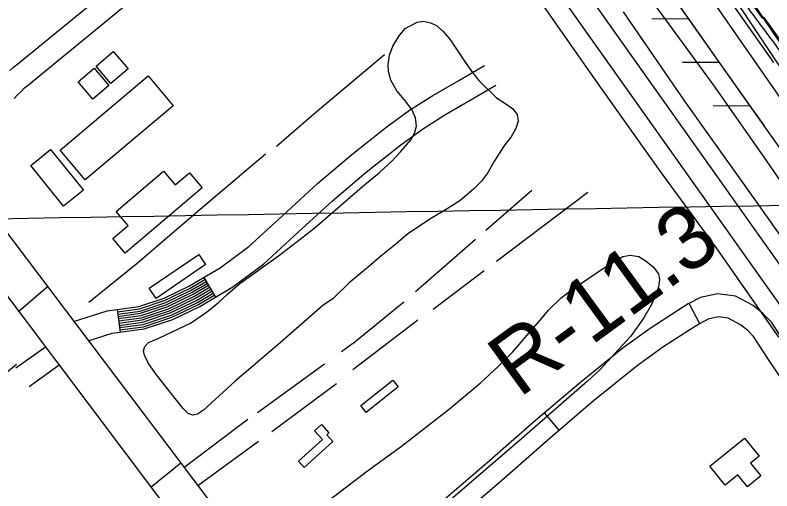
# Model space of a CAD drawing. Extents: x 3892998 to 3931244, y 278583 to 304547.
# Drawn here: x 3909141 to 3910137, y 289921 to 290546 of the extents above; entities that cross this region are included whole.
import ezdxf

# ---------------------------------------------------------------- set-up
doc = ezdxf.new("R2010")
doc.units = 0
for name, color, linetype in [('V-BLDG-OTLN', 7, 'Continuous'), ('V-GRID-MAJR', 7, 'Continuous'), ('V-LEVE-TOET', 7, 'Continuous'), ('V-RIVR-EDGE', 7, 'Continuous'), ('V-RIVR-RANG-IDEN', 7, 'Continuous'), ('V-ROAD-CNTR', 7, 'Continuous'), ('V-RRAP-FSHR', 7, 'Continuous'), ('V-RRAP-RVMT', 7, 'Continuous'), ('V-SITE-VEGE', 7, 'Continuous'), ('V-SURV-LINE', 7, 'Continuous'), ('V-TOPO-MINR', 7, 'Continuous'), ('V-TOPO-SHOR', 7, 'Continuous'), ('V-TOPO-WATR', 7, 'Continuous')]:
    doc.layers.add(name, color=color, linetype=linetype)

msp = doc.modelspace()

# ---------------------------------------------------------------- linework, layer by layer
at = {"layer": 'V-BLDG-OTLN'}
for points in [[(3909270.17, 290498.76), (3909289.69, 290476.08), (3909267.21, 290456.74), (3909247.69, 290479.42)], [(3909245.06, 290476.59), (3909264.48, 290453.81), (3909243.57, 290435.98), (3909224.15, 290458.76)], [(3909349.1, 290427.42), (3909233.34, 290329.81), (3909200.35, 290368.94), (3909316.11, 290466.54)], [(3909187.87, 290369.85), (3909230.97, 290316.39), (3909204.69, 290295.21), (3909161.59, 290348.67)], [(3909387.44, 290319.51), (3909286, 290233.45), (3909269.51, 290252.88), (3909289.75, 290270.06), (3909274.16, 290288.43), (3909336.58, 290341.39), (3909351.87, 290323.38), (3909370.65, 290339.31)], [(3909391.78, 290218.64), (3909326.68, 290174.19), (3909317.67, 290187.39), (3909382.77, 290231.83)], [(3909645.47, 290057.65), (3909603.3, 290024.11), (3909596.14, 290033.12), (3909638.31, 290066.65)], [(3909559.1, 289985.96), (3909521.73, 289951.97), (3909514.27, 289960.17), (3909545.45, 289988.53), (3909535.15, 289999.84), (3909544.25, 290008.13), (3909554.2, 289997.18), (3909551.3, 289994.54)], [(3910055.39, 289953.5), (3910101.26, 289990.48), (3910120.37, 289966.78), (3910108.89, 289957.52), (3910122.43, 289940.72), (3910104.91, 289926.6), (3910092.43, 289942.08), (3910075.57, 289928.48)]]:
    msp.add_lwpolyline(points, close=True, dxfattribs=at)
at = {"layer": 'V-GRID-MAJR'}
msp.add_spline([(3897162.87, 290075.22), (3902475.55, 290165.25), (3907788.21, 290256.05), (3913100.86, 290347.62), (3918413.49, 290439.97), (3923726.11, 290533.09), (3929038.72, 290626.99)], degree=3, dxfattribs=at)
at = {"layer": 'V-LEVE-TOET'}
for points in [[(3910146.31, 290123.1), (3910063.61, 290241.09), (3909990.62, 290340.83), (3909904.47, 290462.04), (3909815.64, 290589.3)], [(3909941.53, 290550.7), (3910022.07, 290433.29), (3910116.71, 290300.67), (3910208.99, 290170.6)]]:
    msp.add_lwpolyline(points, dxfattribs=at)
at = {"layer": 'V-RIVR-EDGE'}
msp.add_spline([(3909865.84, 290928.21), (3909862.62, 290923.11), (3909860.68, 290922.62), (3909860.67, 290920.68), (3909870.35, 290905.12), (3909881.93, 290877.89), (3909893.54, 290856.5), (3909906.13, 290843.84), (3909921.61, 290817.58), (3909937.09, 290794.71), (3909948.22, 290777.2), (3909977.73, 290734.39), (3910003.37, 290694.51), (3910040.65, 290645.85), (3910078.4, 290595.25), (3910114.21, 290544.17), (3910151.48, 290493.58), (3910181.95, 290444.45), (3910200.82, 290413.32), (3910226.93, 290368.58), (3910256.93, 290323.83), (3910278.7, 290289.3), (3910307.74, 290250.37), (3910325.16, 290226.53), (3910363.87, 290167.19), (3910391.44, 290124.87), (3910427.73, 290068.94), (3910449.5, 290036.83), (3910504.18, 289956.56), (3910522.07, 289926.9), (3910550.12, 289879.72), (3910562.21, 289857.35), (3910573.34, 289842.27), (3910610.65, 289806.73), (3910620.82, 289794.07), (3910623.21, 289779.99), (3910634.83, 289764.42), (3910664.83, 289724.03), (3910692.43, 289689.49), (3910710.83, 289668.07), (3910721.01, 289660.28), (3910770.89, 289605.28), (3910782.51, 289588.74), (3910807.66, 289548.37), (3910835.72, 289503.62), (3910862.83, 289470.04), (3910892.35, 289425.78), (3910920.41, 289383.46), (3910947.99, 289342.6), (3910968.78, 289304.67), (3911000.23, 289260.88), (3911019.59, 289231.7), (3911055.91, 289191.3), (3911085.45, 289159.66), (3911118.86, 289116.84), (3911139.19, 289091.05), (3911160.97, 289062.35), (3911184.19, 289025.87), (3911223.42, 288981.58), (3911281.53, 288916.36), (3911313, 288876.94), (3911328.5, 288859.42), (3911346.41, 288837.53), (3911371.58, 288801.04), (3911404.48, 288751.91), (3911426.73, 288715.43), (3911446.57, 288687.7), (3911479.01, 288646.83), (3911529.35, 288582.12), (3911550.65, 288552.92), (3911609.2, 288468.28), (3911644.54, 288421.09), (3911676.97, 288378.76), (3911701.17, 288348.1), (3911741.37, 288303.81), (3911770.9, 288264.88), (3911788.8, 288235.7), (3911834.27, 288164.69), (3911857.49, 288130.15), (3911884.6, 288092.69), (3911915.56, 288045.51), (3911921.85, 288035.78), (3911928.64, 288029.93), (3911972.62, 287945.81), (3911992.92, 287906.42), (3912000.64, 287886.98), (3912014.67, 287866.55), (3912026.77, 287848.06), (3912066.44, 287785.32), (3912084.8, 287750.79), (3912094.47, 287732.8), (3912094.94, 287726), (3912096.85, 287711.43), (3912096.35, 287704.63), (3912095.36, 287700.26), (3912088.55, 287695.91), (3912085.64, 287696.89), (3912073.03, 287702.26), (3912062.35, 287706.17), (3912054.1, 287706.19), (3912051.18, 287704.26), (3912049.22, 287697.95), (3912054.05, 287685.8), (3912068.56, 287663.91), (3912113.05, 287586.58), (3912136.73, 287540.87), (3912153.66, 287513.63), (3912163.84, 287503.9), (3912187.57, 287479.56), (3912207.42, 287453.28), (3912216.14, 287445.98), (3912226.8, 287436.24), (3912240.84, 287416.78), (3912253.42, 287397.81), (3912271.31, 287366.2), (3912283.87, 287341.4), (3912284.84, 287338.97), (3912290.18, 287337.98), (3912303.79, 287344.26), (3912317.4, 287350.54), (3912319.83, 287350.54), (3912322.75, 287350.53), (3912327.59, 287345.66), (3912328.54, 287338.37), (3912335.79, 287321.36), (3912348.36, 287299.96), (3912369.18, 287275.14), (3912380.33, 287265.4), (3912402.15, 287253.21), (3912416.69, 287243.46), (3912434.16, 287238.07), (3912456.94, 287220.05), (3912481.62, 287183.56), (3912501.93, 287148.06), (3912512.56, 287124.73), (3912531.4, 287085.83), (3912550.27, 287059.56), (3912569.64, 287034.26), (3912593.34, 286996.8), (3912613.67, 286968.1), (3912632.04, 286936.49), (3912645.1, 286912.66), (3912660.58, 286888.83), (3912675.09, 286867.42), (3912698.32, 286835.31), (3912720.05, 286784.75), (3912736.96, 286747.81), (3912742.28, 286740.02), (3912755.33, 286715.22), (3912761.6, 286696.75), (3912774.14, 286660.3), (3912779.9, 286635.52), (3912793.38, 286585.46), (3912797.22, 286569.43), (3912803.96, 286543.67), (3912804.41, 286532.02)], degree=3, dxfattribs=at)
at = {"layer": 'V-ROAD-CNTR'}
for p, q in [((3909389.43, 290201.64), (3909404.68, 290175.8)), ((3909275.26, 290159.43), (3909279.29, 290129.71)), ((3910042.2, 290140.9), (3910028.3, 290167.48)), ((3909857.21, 290000.69), (3909837.79, 290023.55))]:
    msp.add_line(p, q, dxfattribs=at)
for points in [[(3905312.49, 295227.11), (3905668.18, 294755.9), (3905995.86, 294324.81), (3906423.56, 293758.76), (3906727.79, 293356.24), (3907205.27, 292726.92), (3907628.01, 292163.31), (3908430.47, 291100.88), (3908883.88, 290504.6), (3909506.66, 289678.12), (3910240.41, 288708.06), (3910610.65, 288220.87)], [(3906034.21, 294352.1), (3906739.31, 293416.78), (3907556.81, 292335.42), (3908052.71, 291678.74), (3908621.74, 290930.17), (3909105.02, 290293.11), (3909494.77, 289778.17), (3910015.52, 289090.83), (3910630.79, 288278.73)], [(3909134.08, 290473.51), (3909139.08, 290477.91), (3909144.72, 290482.56), (3909283.58, 290596.54), (3909308.36, 290617.64), (3909333.43, 290638.69), (3909358.62, 290659.58), (3909383.96, 290680.29), (3909409.44, 290700.84), (3909435.07, 290721.24), (3909454.31, 290736.22), (3909473.36, 290751.23), (3909492.33, 290766.36), (3909511.2, 290781.58), (3909529.98, 290796.92), (3909548.81, 290812.47), (3909559.57, 290821.02), (3909570.41, 290829.4), (3909581.34, 290837.62), (3909592.38, 290845.68), (3909603.5, 290853.59), (3909612.29, 290859.65)], [(3909139.82, 290436.8), (3909144.26, 290441.61), (3909148.86, 290446.25), (3909153.62, 290450.74), (3909158.53, 290455.07), (3909163.77, 290459.39), (3909302.83, 290573.52)], [(3909217.98, 290143.86), (3909262.27, 290157.67), (3909304.12, 290163.35), (3909337.38, 290174.45), (3909369.89, 290190.11), (3909410.91, 290214.32), (3909448.81, 290242.2), (3909493.57, 290283.27), (3909539.03, 290325.02), (3909584.28, 290363.13), (3909630.68, 290399.92), (3909660.24, 290421.38), (3909690.96, 290440.98), (3909725.03, 290460.79), (3909758.83, 290480.44)], [(3909237.22, 290118.44), (3909268.8, 290128.29), (3909310.94, 290134), (3909348.68, 290146.59), (3909384.05, 290163.63), (3909427.47, 290189.25), (3909467.9, 290219), (3909513.85, 290261.17), (3909558.85, 290302.48), (3909603.27, 290339.9), (3909648.82, 290376.02), (3909677.14, 290396.57), (3909706.58, 290415.36), (3909740.11, 290434.85), (3909773.91, 290454.5)], [(3909760.55, 290263.72), (3909821.08, 290316.4)], [(3909895.08, 290313.36), (3909774.6, 290222.48)], [(3909667.94, 290183.12), (3909746.96, 290251.9)], [(3909758.61, 290210.42), (3909691.22, 290159.6)], [(3909275.66, 290156.46), (3909304.8, 290160.41), (3909338.51, 290171.66), (3909371.31, 290187.46), (3909390.95, 290199.05)], [(3909183.6, 290189.29), (3909145.95, 290156.81)], [(3909276.06, 290153.49), (3909305.48, 290157.48), (3909339.64, 290168.88), (3909372.73, 290184.81), (3909392.48, 290196.47)], [(3909276.47, 290150.52), (3909306.17, 290154.54), (3909340.77, 290166.09), (3909374.14, 290182.16), (3909394, 290193.89)], [(3909276.87, 290147.54), (3909306.85, 290151.61), (3909341.9, 290163.3), (3909375.56, 290179.52), (3909395.53, 290191.3)], [(3909277.27, 290144.57), (3909307.53, 290148.67), (3909343.03, 290160.52), (3909376.97, 290176.87), (3909397.05, 290188.72)], [(3909277.68, 290141.6), (3909308.21, 290145.74), (3909344.16, 290157.73), (3909378.39, 290174.22), (3909398.58, 290186.14)], [(3909278.08, 290138.62), (3909308.9, 290142.8), (3909345.29, 290154.95), (3909379.81, 290171.57), (3909400.1, 290183.55)], [(3909278.48, 290135.65), (3909309.58, 290139.87), (3909346.42, 290152.16), (3909381.22, 290168.92), (3909401.63, 290180.97)], [(3910297.94, 289910.12), (3910262.33, 289961.6), (3910220.18, 290020.72), (3910178.28, 290079.51), (3910157.84, 290110.44), (3910136.44, 290142.71), (3910125.39, 290154.48), (3910112.33, 290164.63), (3910089.08, 290176.89), (3910065.51, 290180.3), (3910042.99, 290175.16), (3910027.04, 290166.82), (3910013.16, 290158.32), (3909976.81, 290134.59), (3909941.42, 290109.27), (3909882.98, 290061.93), (3909825.95, 290013.5), (3909793.97, 289985.46), (3909762.14, 289957.55), (3909734.28, 289933.64), (3909706.58, 289910.31)], [(3909278.89, 290132.68), (3909310.26, 290136.93), (3909347.55, 290149.38), (3909382.64, 290166.28), (3909403.15, 290178.39)], [(3909585.46, 290114.74), (3909652.53, 290169.76)], [(3910272.98, 289893.47), (3910237.77, 289944.36), (3910195.75, 290003.3), (3910153.54, 290062.53), (3910132.82, 290093.88), (3910112.84, 290124.02), (3910105.12, 290132.23), (3910096, 290139.32), (3910079.66, 290147.94), (3910066.73, 290149.81), (3910053.45, 290146.78), (3910041.84, 290140.71), (3910029.19, 290132.97), (3909993.74, 290109.82), (3909959.61, 290085.39), (3909902.13, 290038.84), (3909845.55, 289990.79), (3909813.75, 289962.91), (3909781.8, 289934.89), (3909753.71, 289910.79)], [(3909585.46, 290080.82), (3909670.94, 290146.07)], [(3909181.14, 290110.11), (3909142.22, 290082.32)], [(3909570.66, 290104.46), (3909585.46, 290115.18)], [(3909199.2, 290086.15), (3909170.74, 290065.83), (3909159.66, 290057.91)], [(3909460.04, 290024.33), (3909548.09, 290088.11)], [(3909478.76, 289999.3), (3909563.99, 290062.07)], [(3909363.21, 289951.99), (3909435.12, 290006.28), (3909447.58, 290015.3)], [(3909381.43, 289928.16), (3909461.44, 289986.59)], [(3909359, 289957.55), (3909319.96, 289925.89)]]:
    msp.add_lwpolyline(points, dxfattribs=at)
at = {"layer": 'V-RRAP-FSHR'}
for p, q in [((3910027.94, 290541.53), (3909979.11, 290541.34)), ((3910068.31, 290484.35), (3910019.48, 290484.16)), ((3910108.69, 290427.17), (3910059.86, 290426.98))]:
    msp.add_line(p, q, dxfattribs=at)
for points in [[(3906808.74, 295087.99), (3907517.52, 294079.97), (3908118.59, 293281.66), (3908235.46, 293171.33), (3908399.7, 292987.45), (3908497.62, 292843.41), (3908620.81, 292699.37), (3908781.89, 292472.59), (3908840.15, 292360.99), (3908947.12, 292209.3), (3909156.95, 291945.83), (3909268.04, 291726.28), (3910057.13, 290568.32), (3910757.48, 289562.21), (3911229.42, 288921.63), (3911814.1, 288135.16), (3912099.79, 287690.36), (3912357.66, 287495.41), (3912493.3, 287323.29)], [(3911412.62, 288622.24), (3911308.04, 288752.83), (3911327.85, 288790.57), (3910785.78, 289488.37), (3910445.83, 289954.56), (3910129.27, 290398.02), (3909798.59, 290866.33), (3909546.88, 291228.92), (3909473.75, 291330.52), (3909414.69, 291394.46), (3909312.15, 291557.44), (3909036.83, 291981.12), (3908774.4, 292360.28)], [(3910027.94, 290541.53), (3909987.56, 290598.71)], [(3910068.31, 290484.35), (3910027.94, 290541.53)], [(3910108.69, 290427.17), (3910068.31, 290484.35)], [(3910127.27, 290400.85), (3910108.69, 290427.17)]]:
    msp.add_lwpolyline(points, dxfattribs=at)
at = {"layer": 'V-RRAP-RVMT'}
for p, q in [((3910125.11, 290542.17), (3910039.86, 290660.83)), ((3910127.13, 290543.62), (3910125.11, 290542.17)), ((3910156.97, 290501.95), (3910127.13, 290543.62))]:
    msp.add_line(p, q, dxfattribs=at)
at = {"layer": 'V-SITE-VEGE'}
for points in [[(3910177, 290287.64), (3910126.85, 290359.71), (3910060.37, 290454.76), (3909988.46, 290552.83), (3909923.78, 290640.92), (3909885.05, 290694.11), (3909882.34, 290703.03), (3909882.51, 290707.55), (3909885.32, 290714.34), (3909887.96, 290716.62), (3909895.2, 290719.61), (3909912.06, 290725.9), (3909931.76, 290731.72), (3909940.98, 290733.54), (3909948.73, 290734.87), (3909956.6, 290733.84), (3909964.58, 290729.76), (3909971.2, 290723.81), (3910011.32, 290667.29), (3910072.96, 290578.49), (3910139.34, 290484.42)], [(3909544.01, 289901.12), (3909603.14, 289945.91), (3909649.61, 289979.67), (3909713.02, 290029.1), (3909753.23, 290062.62), (3909776.97, 290084.59), (3909796.23, 290103.69), (3909815.18, 290125.93), (3909832.67, 290145.9), (3909843.26, 290158.69), (3909859.7, 290174.85), (3909874.22, 290185.6), (3909915.73, 290214.04), (3909940.79, 290229.17), (3909950.76, 290231), (3909961.93, 290229.2), (3909971.85, 290223.1), (3909981, 290215.42), (3909987.91, 290206.37), (3909989.23, 290198.45), (3909988.01, 290189.34), (3909985.71, 290182.67), (3909978.67, 290165.89), (3909968.69, 290148.7), (3909951.23, 290124.03), (3909910.59, 290080.13), (3909894.63, 290065.35), (3909807.41, 289989.36), (3909716.97, 289911.68)]]:
    msp.add_lwpolyline(points, dxfattribs=at)
msp.add_lwpolyline([(3909546.29, 290164.98), (3909489.74, 290115.89), (3909430.74, 290065.13), (3909389.19, 290027.39), (3909381.1, 290022.05), (3909374.84, 290020.74), (3909369.06, 290022.76), (3909362.16, 290029.37), (3909353.29, 290040.38), (3909327.34, 290073.79), (3909316.68, 290088.7), (3909311.43, 290099.43), (3909310.12, 290105.19), (3909311.75, 290110.98), (3909316.51, 290116.29), (3909330.08, 290121.86), (3909371.75, 290141.49), (3909392.99, 290156.21), (3909408.67, 290168.54), (3909420.54, 290179.57), (3909436.9, 290193.86), (3909487.66, 290230.09), (3909516.4, 290252), (3909536.56, 290267.58), (3909601.29, 290323.96), (3909620.28, 290339.15), (3909637.99, 290355.41), (3909648.2, 290366.63), (3909662.29, 290382.96), (3909667.13, 290392.29), (3909669.23, 290400.62), (3909668.18, 290411.48), (3909663.32, 290422.31), (3909653.45, 290435.37), (3909643.69, 290447.05), (3909635.78, 290461.09), (3909632.38, 290472.23), (3909632.12, 290481.72), (3909633.91, 290493.96), (3909638.14, 290505.54), (3909646.67, 290519.29), (3909654.44, 290528.93), (3909670.34, 290537.35), (3909678.46, 290538.38), (3909687.67, 290536.38), (3909695.72, 290532.71), (3909704.08, 290525.62), (3909713.25, 290515.01), (3909731.52, 290487.52), (3909743.08, 290470.95), (3909751.26, 290460.73), (3909774.79, 290437.97), (3909785.8, 290430.9), (3909795.63, 290423.91), (3909802.04, 290416.02), (3909803.17, 290407.13), (3909800.19, 290397.61), (3909793.8, 290386.71), (3909784.38, 290374.42), (3909772.18, 290354.77), (3909762.68, 290338.86), (3909754.82, 290328.24), (3909744.22, 290317.7), (3909726.21, 290302.52), (3909706.42, 290289.58), (3909687.11, 290278.1), (3909657.38, 290258.74), (3909640.16, 290243.76), (3909622.53, 290229.46), (3909606.07, 290215.65), (3909580.66, 290194.75), (3909559.74, 290174.17)], close=True, dxfattribs=at)
at = {"layer": 'V-SURV-LINE'}
for points in [[(3909350, 291341.39), (3910746.49, 289374.77)], [(3910722.03, 289357.39), (3909325.55, 291324.02)]]:
    msp.add_lwpolyline(points, dxfattribs=at)
at = {"layer": 'V-TOPO-MINR'}
msp.add_lwpolyline([(3909457.77, 291562.76), (3909478.73, 291530.47), (3909499.62, 291498.14), (3909826.54, 290990.79), (3909845.09, 290962.12), (3909863.72, 290933.51), (3909882.46, 290904.96), (3909901.27, 290876.46), (3909920.53, 290847.41), (3909949.09, 290804.47), (3909977.75, 290761.59), (3910006.53, 290718.8), (3910035.41, 290676.07), (3910203.65, 290427.92), (3910222.65, 290399.92), (3910241.68, 290371.94), (3910260.74, 290343.98), (3910279.82, 290316.03), (3910317.89, 290260.33), (3910356.05, 290204.56), (3910394.24, 290148.82), (3910432.48, 290093.1), (3910470.75, 290037.41), (3910655.69, 289768.51)], dxfattribs=at)
at = {"layer": 'V-TOPO-SHOR'}
for points in [[(3909627.29, 290494.42), (3909533.77, 290415.73), (3909485.06, 290374.02)], [(3909470.8, 290363.53), (3909379.14, 290286.23), (3909301.83, 290219.91), (3909238.07, 290168.59)], [(3909143.08, 290087.09), (3909003.1, 289970.47), (3908886.09, 289871.8), (3908785.55, 289785.47)]]:
    msp.add_lwpolyline(points, dxfattribs=at)
at = {"layer": 'V-TOPO-WATR'}
msp.add_lwpolyline([(3909387.65, 291650.53), (3909824.25, 290965.93), (3909837.73, 290944.86), (3909851.27, 290923.82), (3909864.87, 290902.83), (3909878.53, 290881.87), (3909892.25, 290860.95), (3909906.02, 290840.07), (3909919.85, 290819.22), (3909933.73, 290798.41), (3910196.29, 290405.96), (3910211.39, 290383.41), (3910226.52, 290360.88), (3910241.67, 290338.37), (3910256.85, 290315.88), (3910272.07, 290293.41), (3910287.3, 290270.95), (3910302.57, 290248.52), (3910317.86, 290226.1), (3910637.36, 289758.52)], dxfattribs=at)

# ---------------------------------------------------------------- texts
at = {"layer": 'V-RIVR-RANG-IDEN'}
msp.add_text('R-11.3', height=83, rotation=36.09928, dxfattribs=at).set_placement((3909804.41, 290042.31))

doc.saveas('drawing.dxf')
